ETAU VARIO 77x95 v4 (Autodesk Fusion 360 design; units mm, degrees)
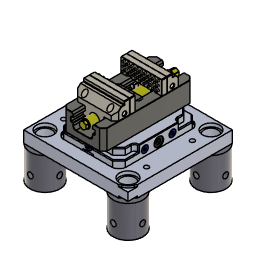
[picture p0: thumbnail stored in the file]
parameter "Ouverture" = 50
base_feature "Base Feature1" OffsetX 0 OffsetY 0 OffsetZ 0
base_feature "Base Feature1"
base_feature "Base Feature1"
base_feature "Base Feature1"
position "Position1"
joint_origin "JointOrigin1" OffsetX 0 OffsetY 0 OffsetZ 0
as_built_joint "As-built1"
as_built_joint "As-built2"
work_axis "WorkAxis1"
work_point "WorkPoint1"
joint_origin "JointOrigin1" OffsetX 0 OffsetY 0 OffsetZ 0
joint "Assemble3" alignOffsetX 0 alignOffsetY 0 alignOffsetZ 25 (= "Ouverture / 2")
joint "Assemble4" alignOffsetX 0 alignOffsetY 0 alignOffsetZ 25 (= "Ouverture / 2")
ground "Ground1"
base_feature "Fonction de base"
position "Position2"
rectangular_pattern "00000000-0000-0000-0000-000000000000" uSpaceDistance -156 vSpaceDistance 156
ground "Terre2"
position "Position3"
ground "Terre3"
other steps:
create_component "CreateComponent1"
create_component "CreateComponent2"
create_component "CreateComponent3"
create_component "CreateComponent4"
joint_origin "JointOrigin4" OffsetX 0 OffsetY 0 OffsetZ 0
joint_origin "JointOrigin5" OffsetX 0 OffsetY 0 OffsetZ 0
create_component "CreateComponent5"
